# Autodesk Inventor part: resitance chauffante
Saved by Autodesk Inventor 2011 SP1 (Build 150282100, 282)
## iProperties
Created: 2010-12
Part Number: resitance chauffante
Document SubType Name: Modeling
Designer: eric
Density: 1 g/cm^3
Author: eric
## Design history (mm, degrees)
feature "Base1"
node "Solide1"
node "Corps solides"
node "Corps surfaciques"
